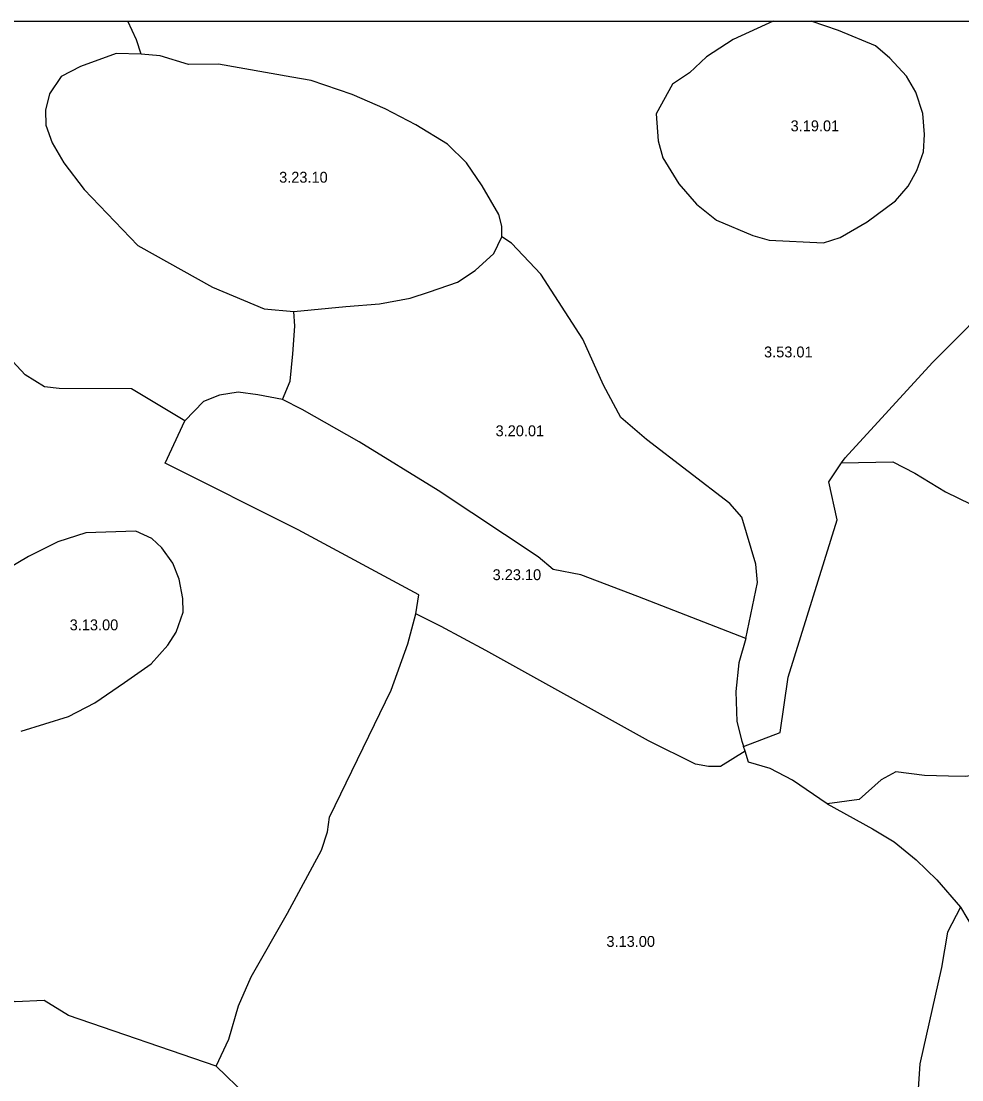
# Model space of a CAD drawing. Extents: x -662500 to -655523, y -1056000 to -1049993.
# Drawn here: x -660777 to -660129, y -1050730 to -1050000 of the extents above; entities that cross this region are included whole.
import ezdxf

# ---------------------------------------------------------------- set-up
doc = ezdxf.new("R2010")
doc.units = 0
doc.layers.add('Vrstva 24', color=7, linetype='Continuous')

msp = doc.modelspace()

# ---------------------------------------------------------------- linework, layer by layer
at = {"layer": 'Vrstva 24'}
for points in [[(-661108.33, -1050000), (-660703.41, -1050000)], [(-660703.41, -1050000), (-660258.66, -1050000)], [(-660694.05, -1050022.74), (-660697.35, -1050012.83), (-660703.41, -1050000)], [(-660258.66, -1050000), (-660286.28, -1050012.66), (-660304.73, -1050024.5), (-660316.3, -1050035.51), (-660328.14, -1050043.5), (-660339.43, -1050063.87), (-660338.05, -1050082.6), (-660334.75, -1050094.16), (-660323.73, -1050112.06), (-660311.62, -1050126.1), (-660297.85, -1050137.12), (-660272.79, -1050147.85), (-660261.5, -1050150.88), (-660224.06, -1050152.81), (-660212.49, -1050149.23), (-660194.04, -1050138.22), (-660174.49, -1050123.9), (-660165.68, -1050113.71), (-660159.62, -1050102.97), (-660155.22, -1050090.03), (-660154.39, -1050078.19), (-660155.49, -1050063.6), (-660160.45, -1050049), (-660166.78, -1050037.99), (-660178.35, -1050025.6), (-660188.26, -1050017.06), (-660213.59, -1050006.33), (-660232.57, -1050000)], [(-660258.66, -1050000), (-660232.57, -1050000)], [(-660232.57, -1050000), (-660083.76, -1050000)], [(-660211.58, -1050304.53), (-660209.05, -1050301.08), (-660148.89, -1050235.27), (-660049.35, -1050135.04), (-660047.7, -1050118.25), (-660049.08, -1050094.01), (-660056.1, -1050060.42), (-660067.94, -1050029.31), (-660083.76, -1050000)], [(-660694.05, -1050022.74), (-660711.4, -1050022.19), (-660735.9, -1050031.28), (-660749.4, -1050038.16), (-660757.38, -1050050), (-660760.13, -1050061.29), (-660759.86, -1050071.75), (-660755.45, -1050083.87), (-660747.47, -1050097.64), (-660733.43, -1050116.08), (-660696.39, -1050154.63), (-660644.9, -1050183.27), (-660609.38, -1050198.41), (-660588.87, -1050200.07)], [(-660445.69, -1050148.58), (-660445.69, -1050141.42), (-660447.75, -1050133.16), (-660459.32, -1050113.61), (-660470.06, -1050097.64), (-660483, -1050084.69), (-660505.02, -1050071.48), (-660525.95, -1050060.46), (-660548.8, -1050050.55), (-660577.03, -1050040.91), (-660590.24, -1050038.71), (-660640.91, -1050029.63), (-660661.56, -1050029.9), (-660681.11, -1050023.84), (-660694.05, -1050022.74)], [(-660664.18, -1050275.51), (-660700.77, -1050253.53), (-660750.63, -1050253.21), (-660760.82, -1050252.11), (-660774.04, -1050243.85), (-660845.22, -1050167.02), (-660903.59, -1050106.45), (-660923.28, -1050086.9), (-660942, -1050064.32), (-661022.68, -1050065.7), (-661044.71, -1050061.84), (-661062.33, -1050061.84), (-661174.26, -1050075.61), (-661192.98, -1050079.46), (-661211.98, -1050080.56), (-661237.17, -1050086.35), (-661249.84, -1050092.13), (-661257.82, -1050099.56), (-661262.78, -1050111.95), (-661263.61, -1050148.02), (-661264.16, -1050162.07)], [(-660588.87, -1050200.07), (-660553.07, -1050196.76), (-660529.94, -1050194.83), (-660508.74, -1050190.98), (-660495.53, -1050186.57), (-660476.25, -1050179.97), (-660464.14, -1050171.98), (-660451.19, -1050160.14), (-660445.69, -1050148.58)], [(-660277.48, -1050425.53), (-660269.49, -1050386.98), (-660270.59, -1050374.32), (-660280.23, -1050341.83), (-660288.49, -1050332.47), (-660346.04, -1050288.41), (-660363.66, -1050273.27), (-660375.5, -1050250.96), (-660389.96, -1050219.3), (-660418.87, -1050174.42), (-660438.97, -1050152.94), (-660445.69, -1050148.58)], [(-660596.72, -1050260.92), (-660591.48, -1050248.25), (-660589.56, -1050229.25), (-660588.18, -1050210.25), (-660588.87, -1050200.07)], [(-660596.72, -1050260.92), (-660613.79, -1050257.61), (-660627.28, -1050255.69), (-660640.22, -1050257.89), (-660651.23, -1050262.29), (-660664.18, -1050275.51)], [(-660277.48, -1050425.53), (-660351.96, -1050396.62), (-660391.33, -1050381.75), (-660410.33, -1050377.9), (-660420.66, -1050369.36), (-660489.49, -1050323.65), (-660544.01, -1050290.06), (-660583.25, -1050267.76), (-660596.72, -1050260.92)], [(-660505.02, -1050408.49), (-660502.82, -1050395.55), (-660585.97, -1050350.67), (-660677.52, -1050304.69), (-660664.18, -1050275.51)], [(-660279.06, -1050499.92), (-660253.8, -1050490.31), (-660248.43, -1050452.27), (-660214.5, -1050343.81), (-660220.28, -1050317.59), (-660211.58, -1050304.53)], [(-660211.58, -1050304.53), (-660176.21, -1050303.89), (-660161.14, -1050311.54), (-660139.94, -1050324.48), (-660079.5, -1050353.94), (-660071.9, -1050356.48), (-660062.88, -1050361.13), (-660056.97, -1050366.88), (-660044.62, -1050380.36)], [(-660776.93, -1050489.46), (-660744.16, -1050479.27), (-660725.99, -1050469.91), (-660705.62, -1050455.86), (-660687.17, -1050442.92), (-660675.88, -1050430.26), (-660670.1, -1050421.17), (-660665.14, -1050407.4), (-660665.41, -1050398.04), (-660667.89, -1050384.55), (-660672.3, -1050373.53), (-660680.01, -1050363.07), (-660686.89, -1050356.74), (-660697.91, -1050351.51), (-660732.32, -1050352.61), (-660751.6, -1050358.94), (-660771.7, -1050369.13), (-660787.53, -1050378.49)], [(-660642.42, -1050720.46), (-660633.74, -1050701.74), (-660627.14, -1050678.88), (-660618.32, -1050658.78), (-660593.27, -1050615), (-660570, -1050571.5), (-660565.87, -1050558.83), (-660564.47, -1050548.78), (-660521.95, -1050461.08), (-660510.53, -1050429.14), (-660505.02, -1050408.49)], [(-660277.89, -1050503.18), (-660295.1, -1050513.92), (-660303.36, -1050513.92), (-660312.17, -1050512.27), (-660344.66, -1050496.02), (-660456.59, -1050433.79), (-660487.43, -1050417.27), (-660505.02, -1050408.49)], [(-660277.48, -1050425.53), (-660282.43, -1050442.33), (-660284.36, -1050462.15), (-660283.81, -1050482.8), (-660280.37, -1050496.3), (-660279.65, -1050498.3), (-660279.06, -1050499.92)], [(-660277.89, -1050503.18), (-660279.06, -1050499.92)], [(-660221.44, -1050539.53), (-660245.4, -1050523.28), (-660260.82, -1050515.3), (-660275.66, -1050510.79), (-660277.89, -1050503.18)], [(-659949.44, -1050675.28), (-659951.05, -1050674.41), (-659962.61, -1050665.27), (-659970.79, -1050636.19), (-659978.9, -1050606.31), (-659978.44, -1050603.2), (-659962.92, -1050562.25), (-659964.85, -1050560.19), (-659964.13, -1050557.42), (-659986.37, -1050535.18), (-659984.16, -1050529.26), (-660000, -1050522.55), (-660004.81, -1050520.51), (-660009.29, -1050518.32), (-660015.01, -1050516.19), (-660035.64, -1050507.45), (-660126.21, -1050520.66), (-660137.96, -1050520.38), (-660154.5, -1050519.99), (-660174.08, -1050517.5), (-660184.27, -1050523.01), (-660199.42, -1050536.5), (-660221.44, -1050539.53)], [(-660221.44, -1050539.53), (-660190.33, -1050556.87), (-660175.32, -1050565.68), (-660160.18, -1050578.08), (-660145.86, -1050591.84), (-660129.53, -1050610.79)], [(-660129.53, -1050610.79), (-660138.7, -1050627.91), (-660142.83, -1050652.42), (-660157.56, -1050718.78), (-660158.98, -1050739.43)], [(-660129.53, -1050610.79), (-660120.8, -1050625.43), (-660108.96, -1050640.58), (-660084.46, -1050681.05), (-660065.46, -1050706.66), (-660062.71, -1050711.62)], [(-660642.42, -1050720.46), (-660744.16, -1050685.49), (-660760.91, -1050675.05), (-660781.05, -1050676.13), (-660841.49, -1050654.65), (-660864.62, -1050650.8), (-660893.26, -1050640.61), (-660913.08, -1050636.75), (-660936.63, -1050635.39)], [(-660497.86, -1050811.32), (-660522.92, -1050801.96), (-660549.07, -1050788.2), (-660596.71, -1050756.81), (-660621.49, -1050740.56), (-660642.42, -1050720.46)]]:
    msp.add_lwpolyline(points, dxfattribs=at)

# ---------------------------------------------------------------- texts
for s, p in [('3.19.01', (-660246.69, -1050075.92)), ('3.23.10', (-660599.1, -1050111.34)), ('3.53.01', (-660264.99, -1050231.79)), ('3.20.01', (-660449.97, -1050286.14)), ('3.23.10', (-660452.02, -1050385.34)), ('3.13.00', (-660743.41, -1050419.92)), ('3.13.00', (-660373.59, -1050638.15))]:
    msp.add_text(s, height=7.5, dxfattribs=at).set_placement(p)

doc.saveas('drawing.dxf')
